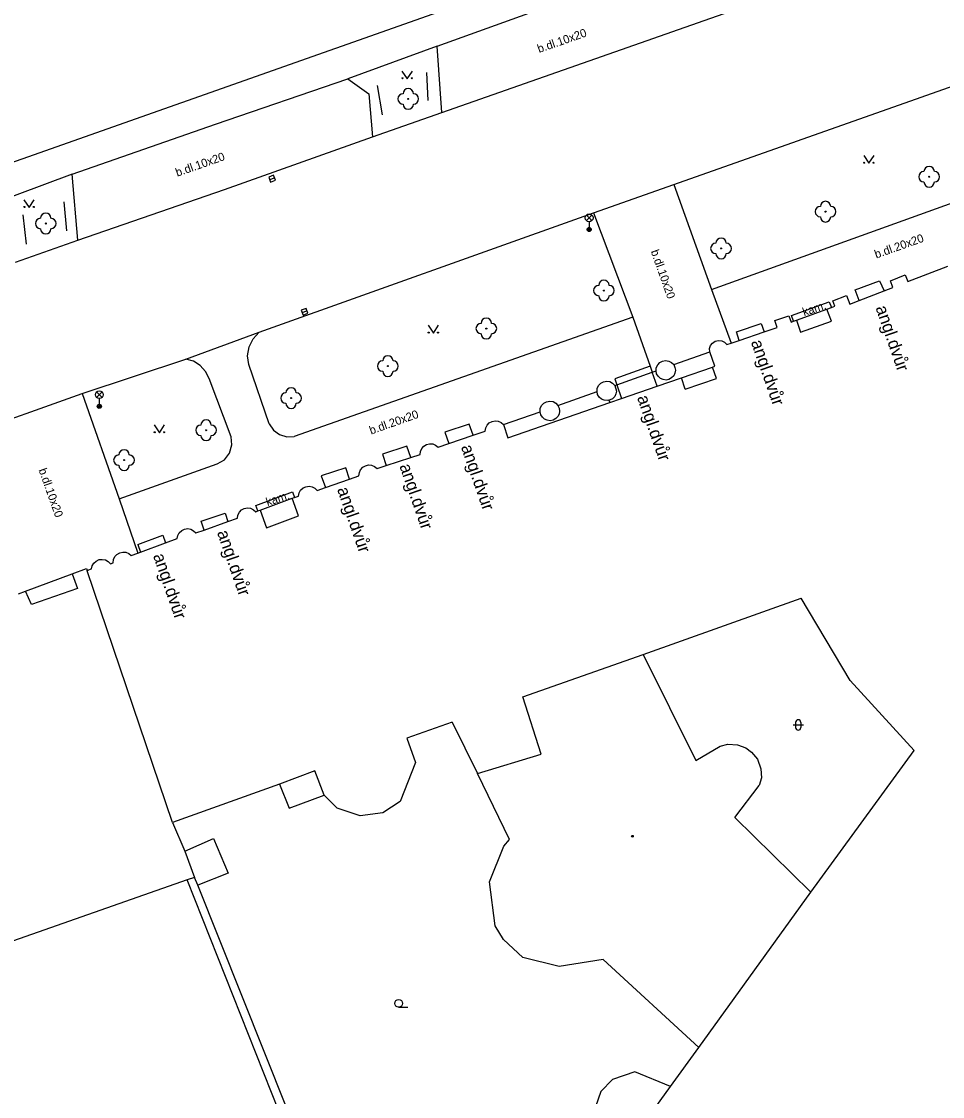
# Model space of a CAD drawing. Extents: x -599770 to -598493, y -1162076 to -1159209.
# Drawn here: x -599015.6 to -598971.2, y -1159443 to -1159391.2 of the extents above; entities that cross this region are included whole.
import ezdxf

# ---------------------------------------------------------------- set-up
doc = ezdxf.new("R2010")
doc.units = 0
doc.layers.add('Podklad', color=7, linetype='Continuous')

msp = doc.modelspace()

# ---------------------------------------------------------------- linework, layer by layer
at = {"layer": 'Podklad'}
for p, q in [((-599003.627, -1159398.855), (-599003.393, -1159398.765)), ((-598988.383, -1159400.83), (-598988.118, -1159400.565)), ((-598988.383, -1159400.565), (-598988.118, -1159400.83)), ((-598988.25, -1159400.885), (-598988.25, -1159401.26)), ((-599002.067, -1159405.265), (-599001.833, -1159405.175)), ((-599011.962, -1159409.35), (-599011.697, -1159409.085)), ((-599011.962, -1159409.085), (-599011.697, -1159409.35)), ((-599011.83, -1159409.405), (-599011.83, -1159409.78)), ((-598978.433, -1159425.128), (-598977.933, -1159425.128)), ((-598978.308, -1159425.003), (-598978.308, -1159425.253)), ((-598978.058, -1159425.003), (-598978.058, -1159425.253)), ((-598997.42, -1159438.727), (-598996.983, -1159438.727))]:
    msp.add_line(p, q, dxfattribs=at)
for points in [[(-599066.08, -1159415.71), (-599053.26, -1159411.13), (-599037.8, -1159405.7), (-598985.61, -1159387.27)], [(-598995.56, -1159392.43), (-598982.51, -1159387.71)], [(-598995.34, -1159395.63), (-598981.16, -1159390.65)], [(-598995.56, -1159392.43), (-598999.87, -1159394)], [(-598995.34, -1159395.63), (-598995.56, -1159392.43)], [(-598984.17, -1159399.1), (-598966.31, -1159392.78)], [(-598997.26, -1159393.625), (-598997.01, -1159394), (-598996.76, -1159393.625)], [(-599013.13, -1159398.59), (-599006.24, -1159396.18), (-598999.87, -1159394)], [(-598999.87, -1159394), (-598998.85, -1159394.73), (-598998.68, -1159396.79)], [(-598996.08, -1159393.69), (-598996.01, -1159395.05)], [(-598998.45, -1159394.32), (-598998.21, -1159395.73)], [(-598998.68, -1159396.79), (-598995.34, -1159395.63)], [(-599012.86, -1159401.77), (-599005.81, -1159399.33), (-598998.68, -1159396.79)], [(-598975.03, -1159397.695), (-598974.78, -1159398.07), (-598974.53, -1159397.695)], [(-599013.13, -1159398.59), (-599017.15, -1159400.09)], [(-599012.86, -1159401.77), (-599013.13, -1159398.59)], [(-598982.36, -1159404.15), (-598967.11, -1159398.66)], [(-598988.04, -1159400.45), (-598984.17, -1159399.1)], [(-598984.17, -1159399.1), (-598982.36, -1159404.15)], [(-599015.46, -1159399.825), (-599015.21, -1159400.2), (-599014.96, -1159399.825)], [(-599013.54, -1159399.92), (-599013.41, -1159401.32)], [(-599015.52, -1159400.55), (-599015.36, -1159401.96)], [(-599004.13, -1159406.2), (-598988.04, -1159400.45)], [(-598988.04, -1159400.45), (-598986.14, -1159405.49)], [(-599015.86, -1159402.84), (-599012.86, -1159401.77)], [(-598973.75, -1159403.73), (-598973.03, -1159403.45)], [(-598973.03, -1159403.45), (-598972.91, -1159403.77)], [(-598972.91, -1159403.77), (-598970.98, -1159403.02)], [(-598975.25, -1159404.68), (-598975.45, -1159404.17), (-598974.27, -1159403.74), (-598974.05, -1159404.21)], [(-598973.63, -1159404.05), (-598973.75, -1159403.73)], [(-598982.36, -1159404.15), (-598981.42, -1159406.73)], [(-598976.52, -1159404.7), (-598975.86, -1159404.44)], [(-598975.86, -1159404.44), (-598975.7, -1159404.85)], [(-598975.7, -1159404.85), (-598975.25, -1159404.68), (-598974.05, -1159404.21), (-598973.63, -1159404.05)], [(-598978.42, -1159405.68), (-598978.51, -1159405.41), (-598976.69, -1159404.74), (-598976.58, -1159405.02)], [(-598978.42, -1159405.68), (-598978.51, -1159405.41), (-598976.69, -1159404.74), (-598976.58, -1159405.01)], [(-598976.8, -1159405.1), (-598976.58, -1159405.01), (-598976.42, -1159404.95)], [(-598976.42, -1159404.95), (-598976.52, -1159404.7)], [(-598986.14, -1159405.49), (-599002.45, -1159411.23)], [(-598986.14, -1159405.49), (-598985.32, -1159407.85), (-598985.22, -1159408.14)], [(-598979.31, -1159405.65), (-598978.63, -1159405.42)], [(-598978.63, -1159405.42), (-598978.53, -1159405.72)], [(-598978.27, -1159405.63), (-598976.8, -1159405.1)], [(-598976.59, -1159405.67), (-598976.8, -1159405.1)], [(-598996, -1159405.875), (-598995.75, -1159406.25), (-598995.5, -1159405.875)], [(-598981.42, -1159406.73), (-598981.03, -1159406.6), (-598979.83, -1159406.19), (-598979.2, -1159405.98)], [(-598981.16, -1159406.19), (-598979.97, -1159405.78), (-598979.83, -1159406.19)], [(-598979.2, -1159405.98), (-598979.31, -1159405.65)], [(-598978.53, -1159405.72), (-598978.42, -1159405.68), (-598978.27, -1159405.63)], [(-598978.27, -1159405.63), (-598978.07, -1159406.2)], [(-598978.07, -1159406.2), (-598976.59, -1159405.67)], [(-599007.67, -1159407.51), (-599004.13, -1159406.2)], [(-599004.63, -1159407.77), (-599004.69, -1159407.34), (-599004.62, -1159406.91), (-599004.43, -1159406.52), (-599004.13, -1159406.2)], [(-598981.03, -1159406.6), (-598981.16, -1159406.19)], [(-598982.45, -1159407), (-598982.4, -1159406.85)], [(-598982.44, -1159407.16), (-598982.45, -1159407)], [(-598982.4, -1159406.85), (-598982.31, -1159406.73)], [(-598982.31, -1159406.73), (-598982.18, -1159406.64)], [(-598982.18, -1159406.64), (-598982.03, -1159406.6)], [(-598982.03, -1159406.6), (-598981.87, -1159406.62)], [(-598981.87, -1159406.62), (-598981.73, -1159406.69)], [(-598981.73, -1159406.69), (-598981.62, -1159406.8)], [(-598981.62, -1159406.8), (-598981.42, -1159406.73)], [(-599012.65, -1159409.16), (-599007.67, -1159407.51)], [(-599006.55, -1159408.44), (-599006.72, -1159408.1), (-599006.98, -1159407.81), (-599007.3, -1159407.61), (-599007.67, -1159407.51)], [(-598984.85, -1159407.67), (-598984.72, -1159407.6)], [(-598984.72, -1159407.6), (-598984.57, -1159407.57)], [(-598984.57, -1159407.57), (-598984.42, -1159407.6)], [(-598984.42, -1159407.6), (-598984.29, -1159407.66)], [(-598984.18, -1159407.77), (-598982.44, -1159407.16)], [(-598982.2, -1159407.85), (-598982.44, -1159407.16)], [(-599003.66, -1159410.62), (-599004.63, -1159407.77)], [(-598985.32, -1159407.85), (-598987.01, -1159408.46), (-598986.91, -1159408.74)], [(-598986.91, -1159408.74), (-598985.22, -1159408.14)], [(-598985.22, -1159408.14), (-598985.03, -1159408.07)], [(-598984.98, -1159408.81), (-598985.22, -1159408.14)], [(-598985.03, -1159408.07), (-598985.02, -1159407.92)], [(-598985, -1159408.21), (-598985.03, -1159408.07)], [(-598985.02, -1159407.92), (-598984.95, -1159407.78)], [(-598984.95, -1159407.78), (-598984.85, -1159407.67)], [(-598984.29, -1159407.66), (-598984.18, -1159407.77)], [(-598984.18, -1159407.77), (-598984.12, -1159407.9)], [(-598984.12, -1159407.9), (-598984.1, -1159408.04)], [(-598984.1, -1159408.04), (-598984.12, -1159408.18)], [(-598983.81, -1159408.41), (-598982.31, -1159407.89)], [(-598982.31, -1159407.89), (-598982.2, -1159407.85)], [(-598982.12, -1159408.43), (-598982.31, -1159407.89)], [(-599005.49, -1159411.24), (-599006.55, -1159408.44)], [(-598992.16, -1159411.29), (-598987.26, -1159409.6), (-598986.69, -1159409.4), (-598984.98, -1159408.81), (-598983.81, -1159408.41)], [(-598987.8, -1159408.77), (-598987.69, -1159408.66)], [(-598987.69, -1159408.66), (-598987.56, -1159408.59)], [(-598987.56, -1159408.59), (-598987.4, -1159408.56)], [(-598987.4, -1159408.56), (-598987.25, -1159408.58)], [(-598987.25, -1159408.58), (-598987.12, -1159408.66)], [(-598987.12, -1159408.66), (-598987.01, -1159408.77)], [(-598984.93, -1159408.33), (-598985, -1159408.21)], [(-598984.82, -1159408.43), (-598984.93, -1159408.33)], [(-598984.69, -1159408.49), (-598984.82, -1159408.43)], [(-598984.55, -1159408.51), (-598984.69, -1159408.49)], [(-598984.41, -1159408.48), (-598984.55, -1159408.51)], [(-598984.28, -1159408.41), (-598984.41, -1159408.48)], [(-598984.18, -1159408.31), (-598984.28, -1159408.41)], [(-598984.12, -1159408.18), (-598984.18, -1159408.31)], [(-598983.62, -1159408.95), (-598983.81, -1159408.41)], [(-598983.62, -1159408.95), (-598982.12, -1159408.43)], [(-599018.33, -1159411.18), (-599012.65, -1159409.16)], [(-599012.65, -1159409.16), (-599010.88, -1159414.23)], [(-598989.75, -1159409.74), (-598987.87, -1159409.07)], [(-598987.87, -1159409.07), (-598987.86, -1159408.92)], [(-598987.84, -1159409.21), (-598987.87, -1159409.07)], [(-598987.86, -1159408.92), (-598987.8, -1159408.77)], [(-598986.96, -1159409.18), (-598987.02, -1159409.31)], [(-598987.01, -1159408.77), (-598986.91, -1159408.74)], [(-598987.01, -1159408.77), (-598986.93, -1159409.04)], [(-598986.93, -1159409.04), (-598986.96, -1159409.18)], [(-598986.915, -1159408.736), (-598986.69, -1159409.4)], [(-598990.54, -1159409.74), (-598990.43, -1159409.63)], [(-598990.43, -1159409.63), (-598990.3, -1159409.56)], [(-598990.3, -1159409.56), (-598990.14, -1159409.53)], [(-598990.14, -1159409.53), (-598989.99, -1159409.55)], [(-598989.99, -1159409.55), (-598989.86, -1159409.63)], [(-598989.86, -1159409.63), (-598989.75, -1159409.74)], [(-598987.76, -1159409.33), (-598987.84, -1159409.21)], [(-598987.66, -1159409.43), (-598987.76, -1159409.33)], [(-598987.53, -1159409.48), (-598987.66, -1159409.43)], [(-598987.39, -1159409.5), (-598987.53, -1159409.48)], [(-598987.24, -1159409.47), (-598987.3, -1159409.48), (-598987.39, -1159409.5)], [(-598987.3, -1159409.48), (-598987.26, -1159409.6)], [(-598987.12, -1159409.41), (-598987.24, -1159409.47)], [(-598987.02, -1159409.31), (-598987.12, -1159409.41)], [(-598992.38, -1159410.66), (-598990.61, -1159410.04)], [(-598990.61, -1159410.04), (-598990.6, -1159409.89)], [(-598990.58, -1159410.18), (-598990.61, -1159410.04)], [(-598990.6, -1159409.89), (-598990.54, -1159409.74)], [(-598990.5, -1159410.3), (-598990.58, -1159410.18)], [(-598989.7, -1159410.15), (-598989.76, -1159410.27)], [(-598989.75, -1159409.74), (-598989.69, -1159409.87)], [(-598989.67, -1159410.01), (-598989.7, -1159410.15)], [(-598989.69, -1159409.87), (-598989.67, -1159410.01)], [(-599009.19, -1159410.675), (-599008.94, -1159411.05), (-599008.69, -1159410.675)], [(-599003.66, -1159410.62), (-599003.45, -1159410.92), (-599003.16, -1159411.13), (-599002.81, -1159411.24), (-599002.45, -1159411.23)], [(-598993.84, -1159411.17), (-598994.02, -1159410.64), (-598995.19, -1159411.03), (-598995, -1159411.57)], [(-598993.23, -1159410.82), (-598993.16, -1159410.69)], [(-598993.16, -1159410.69), (-598993.06, -1159410.58)], [(-598993.06, -1159410.58), (-598992.92, -1159410.51)], [(-598992.92, -1159410.51), (-598992.78, -1159410.48)], [(-598992.78, -1159410.48), (-598992.63, -1159410.5)], [(-598992.63, -1159410.5), (-598992.49, -1159410.56)], [(-598992.49, -1159410.56), (-598992.38, -1159410.66)], [(-598992.38, -1159410.66), (-598992.16, -1159411.29)], [(-598990.4, -1159410.39), (-598990.5, -1159410.3)], [(-598990.27, -1159410.45), (-598990.4, -1159410.39)], [(-598990.13, -1159410.47), (-598990.27, -1159410.45)], [(-598989.99, -1159410.44), (-598990.13, -1159410.47)], [(-598989.86, -1159410.37), (-598989.99, -1159410.44)], [(-598989.76, -1159410.27), (-598989.86, -1159410.37)], [(-599006.16, -1159412.55), (-599005.81, -1159412.35), (-599005.56, -1159412.03), (-599005.45, -1159411.64), (-599005.49, -1159411.24)], [(-598995.52, -1159411.75), (-598995, -1159411.57), (-598993.84, -1159411.17), (-598993.26, -1159410.97)], [(-598993.26, -1159410.97), (-598993.23, -1159410.82)], [(-598996.84, -1159412.25), (-598997.02, -1159411.69), (-598998.2, -1159412.09), (-598998.02, -1159412.63)], [(-598996.31, -1159411.81), (-598996.21, -1159411.69)], [(-598996.21, -1159411.69), (-598996.08, -1159411.62)], [(-598996.08, -1159411.62), (-598995.93, -1159411.58)], [(-598995.93, -1159411.58), (-598995.78, -1159411.59)], [(-598995.78, -1159411.59), (-598995.64, -1159411.65)], [(-598995.64, -1159411.65), (-598995.52, -1159411.75)], [(-598998.46, -1159412.77), (-598998.02, -1159412.63), (-598996.84, -1159412.25), (-598996.39, -1159412.1)], [(-598996.39, -1159412.1), (-598996.37, -1159411.95)], [(-598996.37, -1159411.95), (-598996.31, -1159411.81)], [(-599010.88, -1159414.23), (-599006.16, -1159412.55)], [(-598999.78, -1159413.28), (-598999.97, -1159412.74), (-599001.15, -1159413.12), (-599000.95, -1159413.69)], [(-598999.25, -1159412.83), (-598999.15, -1159412.71)], [(-598999.15, -1159412.71), (-598999.02, -1159412.64)], [(-598999.02, -1159412.64), (-598998.87, -1159412.6)], [(-598998.87, -1159412.6), (-598998.72, -1159412.61)], [(-598998.72, -1159412.61), (-598998.58, -1159412.67)], [(-598998.58, -1159412.67), (-598998.46, -1159412.77)], [(-599001.34, -1159413.83), (-599000.95, -1159413.69), (-598999.78, -1159413.28), (-598999.33, -1159413.12)], [(-598999.33, -1159413.12), (-598999.31, -1159412.97)], [(-598999.31, -1159412.97), (-598999.25, -1159412.83)], [(-599002.21, -1159413.95), (-599002.14, -1159413.82)], [(-599002.14, -1159413.82), (-599002.02, -1159413.71)], [(-599002.02, -1159413.71), (-599001.89, -1159413.65)], [(-599001.89, -1159413.65), (-599001.73, -1159413.62)], [(-599001.73, -1159413.62), (-599001.58, -1159413.65)], [(-599001.58, -1159413.65), (-599001.45, -1159413.72)], [(-599001.45, -1159413.72), (-599001.34, -1159413.83)], [(-599010.88, -1159414.23), (-599009.98, -1159416.85)], [(-599004.2, -1159414.82), (-599004.3, -1159414.56), (-599002.53, -1159413.89), (-599002.44, -1159414.17)], [(-599004.2, -1159414.82), (-599004.3, -1159414.56), (-599002.53, -1159413.89), (-599002.44, -1159414.17)], [(-599004.08, -1159414.78), (-599002.54, -1159414.2)], [(-599002.54, -1159414.2), (-599002.44, -1159414.17), (-599002.24, -1159414.1)], [(-599002.24, -1159415.05), (-599002.54, -1159414.2)], [(-599002.24, -1159414.1), (-599002.21, -1159413.95)], [(-599005.16, -1159415.02), (-599005.09, -1159414.88)], [(-599005.09, -1159414.88), (-599004.99, -1159414.77)], [(-599004.99, -1159414.77), (-599004.85, -1159414.7)], [(-599004.85, -1159414.7), (-599004.7, -1159414.67)], [(-599004.7, -1159414.67), (-599004.55, -1159414.69)], [(-599004.55, -1159414.69), (-599004.41, -1159414.76)], [(-599004.41, -1159414.76), (-599004.3, -1159414.86)], [(-599004.3, -1159414.86), (-599004.2, -1159414.82), (-599004.08, -1159414.78)], [(-599004.08, -1159414.78), (-599003.78, -1159415.63)], [(-599007.18, -1159415.88), (-599006.78, -1159415.74), (-599005.64, -1159415.33), (-599005.18, -1159415.17)], [(-599006.78, -1159415.74), (-599006.93, -1159415.31), (-599005.78, -1159414.93), (-599005.64, -1159415.33)], [(-599005.18, -1159415.17), (-599005.16, -1159415.02)], [(-599003.78, -1159415.63), (-599002.24, -1159415.05)], [(-599008.05, -1159416), (-599007.98, -1159415.87)], [(-599007.98, -1159415.87), (-599007.86, -1159415.76)], [(-599007.86, -1159415.76), (-599007.73, -1159415.7)], [(-599007.73, -1159415.7), (-599007.57, -1159415.67)], [(-599007.57, -1159415.67), (-599007.42, -1159415.7)], [(-599007.42, -1159415.7), (-599007.29, -1159415.77)], [(-599007.29, -1159415.77), (-599007.18, -1159415.88)], [(-599009.98, -1159416.43), (-599008.77, -1159415.99), (-599008.64, -1159416.36)], [(-599009.98, -1159416.85), (-599009.85, -1159416.8), (-599008.64, -1159416.36), (-599008.08, -1159416.15)], [(-599009.98, -1159416.43), (-599009.85, -1159416.8)], [(-599008.08, -1159416.15), (-599008.05, -1159416)], [(-599011.08, -1159417.02), (-599010.98, -1159416.91)], [(-599010.98, -1159416.91), (-599010.85, -1159416.83)], [(-599010.85, -1159416.83), (-599010.7, -1159416.8)], [(-599010.7, -1159416.8), (-599010.55, -1159416.81)], [(-599010.55, -1159416.81), (-599010.41, -1159416.87)], [(-599010.41, -1159416.87), (-599010.29, -1159416.97)], [(-599010.29, -1159416.97), (-599009.98, -1159416.85)], [(-599012.2, -1159417.61), (-599012.17, -1159417.46)], [(-599012.17, -1159417.46), (-599012.09, -1159417.33)], [(-599012.09, -1159417.33), (-599011.98, -1159417.23)], [(-599011.98, -1159417.23), (-599011.84, -1159417.16)], [(-599011.84, -1159417.16), (-599011.69, -1159417.15)], [(-599011.69, -1159417.15), (-599011.54, -1159417.18)], [(-599011.54, -1159417.18), (-599011.41, -1159417.25)], [(-599011.41, -1159417.25), (-599011.3, -1159417.36)], [(-599011.3, -1159417.36), (-599011.16, -1159417.31)], [(-599011.16, -1159417.31), (-599011.14, -1159417.16)], [(-599011.14, -1159417.16), (-599011.08, -1159417.02)], [(-599015.72, -1159418.81), (-599015.39, -1159418.69), (-599013.13, -1159417.84), (-599012.45, -1159417.59)], [(-599013.13, -1159417.84), (-599012.88, -1159418.55), (-599015.09, -1159419.32), (-599015.39, -1159418.69)], [(-599012.45, -1159417.59), (-599012.41, -1159417.7)], [(-599012.2, -1159417.61), (-599012.41, -1159417.7)], [(-599008.31, -1159429.83), (-599012.41, -1159417.7)], [(-598985.65, -1159421.73), (-598978.05, -1159419.02)], [(-598975.69, -1159422.99), (-598978.05, -1159419.02)], [(-598991.44, -1159423.78), (-598985.65, -1159421.73)], [(-598985.65, -1159421.73), (-598983.12, -1159426.84)], [(-598972.6, -1159426.36), (-598975.69, -1159422.99)], [(-598990.56, -1159426.53), (-598991.44, -1159423.78)], [(-598994.84, -1159424.99), (-598997.03, -1159425.77)], [(-598994.84, -1159424.99), (-598993.63, -1159427.47)], [(-598997.03, -1159425.77), (-598996.61, -1159426.94)], [(-598983.12, -1159426.84), (-598981.95, -1159426.15)], [(-598981.95, -1159426.15), (-598981.57, -1159426.06)], [(-598981.57, -1159426.06), (-598981.11, -1159426.08)], [(-598981.11, -1159426.08), (-598980.71, -1159426.23)], [(-598980.71, -1159426.23), (-598980.43, -1159426.43)], [(-598993.63, -1159427.47), (-598990.56, -1159426.53)], [(-598980.43, -1159426.43), (-598980.14, -1159426.78)], [(-598980.14, -1159426.78), (-598979.98, -1159427.24)], [(-598977.57, -1159433.18), (-598972.6, -1159426.36)], [(-598996.61, -1159426.94), (-598997.34, -1159428.81)], [(-598979.98, -1159427.24), (-598979.96, -1159427.68)], [(-599001.46, -1159427.34), (-599003.16, -1159427.98)], [(-599001, -1159428.51), (-599001.46, -1159427.34)], [(-598992.08, -1159430.65), (-598993.63, -1159427.47)], [(-598979.96, -1159427.68), (-598980.07, -1159428.05)], [(-599003.16, -1159427.98), (-599008.31, -1159429.83)], [(-599003.16, -1159427.98), (-599002.69, -1159429.14)], [(-598981.24, -1159429.59), (-598980.07, -1159428.05)], [(-599002.69, -1159429.14), (-599001, -1159428.51)], [(-599000.38, -1159429.13), (-599001, -1159428.51)], [(-598997.34, -1159428.81), (-598998.18, -1159429.36)], [(-598999.28, -1159429.5), (-599000.38, -1159429.13)], [(-598998.18, -1159429.36), (-598999.28, -1159429.5)], [(-599008.31, -1159429.83), (-599007.72, -1159431.2)], [(-598977.57, -1159433.18), (-598981.24, -1159429.59)], [(-599007.72, -1159431.2), (-599006.34, -1159430.6)], [(-599006.34, -1159430.6), (-599005.62, -1159432.26)], [(-598992.35, -1159430.96), (-598992.08, -1159430.65)], [(-599007.72, -1159431.2), (-599007.25, -1159432.47)], [(-598993.04, -1159432.69), (-598992.35, -1159430.96)], [(-599007.25, -1159432.47), (-599007.6, -1159432.58)], [(-599007.09, -1159432.85), (-599007.25, -1159432.47)], [(-599005.62, -1159432.26), (-599007.09, -1159432.85)], [(-599007.6, -1159432.58), (-599022.28, -1159437.74)], [(-599003.17, -1159443.76), (-599007.6, -1159432.58)], [(-599002.82, -1159443.55), (-599007.09, -1159432.85)], [(-598992.78, -1159434.81), (-598993.04, -1159432.69)], [(-598982.97, -1159440.67), (-598977.57, -1159433.18)], [(-598992.38, -1159435.47), (-598992.78, -1159434.81)], [(-598991.45, -1159436.33), (-598992.38, -1159435.47)], [(-598989.69, -1159436.76), (-598991.45, -1159436.33)], [(-598987.58, -1159436.42), (-598989.69, -1159436.76)], [(-598982.97, -1159440.67), (-598987.58, -1159436.42)], [(-598984.34, -1159442.55), (-598982.97, -1159440.67)], [(-598987.13, -1159442.21), (-598987.68, -1159442.78)], [(-598986.05, -1159441.83), (-598987.13, -1159442.21)], [(-598984.34, -1159442.55), (-598986.05, -1159441.83)], [(-598987.68, -1159442.78), (-598988.19, -1159444.22)], [(-598986.82, -1159446), (-598984.34, -1159442.55)]]:
    msp.add_lwpolyline(points, dxfattribs=at)
for points in [[(-599003.582, -1159398.972), (-599003.348, -1159398.882), (-599003.438, -1159398.648), (-599003.672, -1159398.738)], [(-599002.022, -1159405.382), (-599001.788, -1159405.291), (-599001.878, -1159405.058), (-599002.112, -1159405.148)]]:
    msp.add_lwpolyline(points, close=True, dxfattribs=at)
for centre, radius in [((-598997.235, -1159393.975), 0.025), ((-598996.785, -1159393.975), 0.025), ((-598996.96, -1159394.97), 0.025), ((-598975.005, -1159398.045), 0.025), ((-598974.555, -1159398.045), 0.025), ((-598971.88, -1159398.72), 0.025), ((-599015.435, -1159400.175), 0.025), ((-599014.985, -1159400.175), 0.025), ((-598976.87, -1159400.4), 0.025), ((-598988.25, -1159400.698), 0.188), ((-599014.41, -1159400.97), 0.025), ((-598988.25, -1159401.26), 0.1), ((-598988.25, -1159401.26), 0.0723), ((-598988.25, -1159401.26), 0.0438), ((-598981.9, -1159402.17), 0.025), ((-598987.54, -1159404.2), 0.025), ((-598993.2, -1159406.03), 0.025), ((-598995.975, -1159406.225), 0.025), ((-598995.525, -1159406.225), 0.025), ((-598997.94, -1159407.84), 0.025), ((-599011.83, -1159409.218), 0.188), ((-599011.83, -1159409.78), 0.1), ((-599002.6, -1159409.38), 0.025), ((-599011.83, -1159409.78), 0.0723), ((-599011.83, -1159409.78), 0.0438), ((-599009.165, -1159411.025), 0.025), ((-599008.715, -1159411.025), 0.025), ((-599006.69, -1159410.93), 0.025), ((-599010.64, -1159412.37), 0.025), ((-598986.17, -1159430.49), 0.045), ((-598986.17, -1159430.49), 0.0199), ((-598997.42, -1159438.54), 0.188)]:
    msp.add_circle(centre, radius, dxfattribs=at)
for centre, radius, start, end in [((-598996.96, -1159394.72), 0.25, 0, 180), ((-598997.21, -1159394.97), 0.25, 90, 270), ((-598996.71, -1159394.97), 0.25, 270, 90), ((-598996.96, -1159395.22), 0.25, 180, 0), ((-598971.88, -1159398.47), 0.25, 0, 180), ((-598972.13, -1159398.72), 0.25, 90, 270), ((-598971.63, -1159398.72), 0.25, 270, 90), ((-598971.88, -1159398.97), 0.25, 180, 0), ((-598977.12, -1159400.4), 0.25, 90, 270), ((-598976.87, -1159400.15), 0.25, 0, 180), ((-598976.62, -1159400.4), 0.25, 270, 90), ((-599014.66, -1159400.97), 0.25, 90, 270), ((-599014.41, -1159400.72), 0.25, 0, 180), ((-599014.16, -1159400.97), 0.25, 270, 90), ((-598976.87, -1159400.65), 0.25, 180, 0), ((-599014.41, -1159401.22), 0.25, 180, 0), ((-598982.15, -1159402.17), 0.25, 90, 270), ((-598981.9, -1159401.92), 0.25, 0, 180), ((-598981.65, -1159402.17), 0.25, 270, 90), ((-598981.9, -1159402.42), 0.25, 180, 0), ((-598987.79, -1159404.2), 0.25, 90, 270), ((-598987.54, -1159403.95), 0.25, 0, 180), ((-598987.29, -1159404.2), 0.25, 270, 90), ((-598987.54, -1159404.45), 0.25, 180, 0), ((-598993.2, -1159405.78), 0.25, 0, 180), ((-598993.45, -1159406.03), 0.25, 90, 270), ((-598992.95, -1159406.03), 0.25, 270, 90), ((-598993.2, -1159406.28), 0.25, 180, 0), ((-598998.19, -1159407.84), 0.25, 90, 270), ((-598997.94, -1159407.59), 0.25, 0, 180), ((-598997.69, -1159407.84), 0.25, 270, 90), ((-598997.94, -1159408.09), 0.25, 180, 0), ((-599002.85, -1159409.38), 0.25, 90, 270), ((-599002.6, -1159409.13), 0.25, 0, 180), ((-599002.35, -1159409.38), 0.25, 270, 90), ((-599002.6, -1159409.63), 0.25, 180, 0), ((-599006.94, -1159410.93), 0.25, 90, 270), ((-599006.69, -1159410.68), 0.25, 0, 180), ((-599006.44, -1159410.93), 0.25, 270, 90), ((-599006.69, -1159411.18), 0.25, 180, 0), ((-599010.89, -1159412.37), 0.25, 90, 270), ((-599010.64, -1159412.12), 0.25, 0, 180), ((-599010.39, -1159412.37), 0.25, 270, 90), ((-599010.64, -1159412.62), 0.25, 180, 0), ((-598978.183, -1159425.003), 0.125, 0, 180), ((-598978.183, -1159425.253), 0.125, 180, 0)]:
    msp.add_arc(centre, radius, start, end, dxfattribs=at)

# ---------------------------------------------------------------- texts
for s, height, rotation, p in [('b.dl.10x20', 0.4, 19.3035, (-598990.66, -1159392.76)), ('b.dl.10x20', 0.4, 19.3035, (-599008.08, -1159398.72)), ('b.dl.20x20', 0.4, 19.5159, (-598974.43, -1159402.66)), ('b.dl.10x20', 0.4, 289.5159, (-598985.29, -1159402.31)), ('kam.', 0.4, 18.5793, (-598977.9, -1159405.44)), ('angl.dvůr', 0.6, 289.1291, (-598974.47, -1159405.03)), ('angl.dvůr', 0.6, 289.1291, (-598980.47, -1159406.68)), ('angl.dvůr', 0.6, 289.1291, (-598985.95, -1159409.35)), ('b.dl.20x20', 0.4, 19.5159, (-598998.75, -1159411.14)), ('angl.dvůr', 0.6, 289.1291, (-598994.43, -1159411.73)), ('b.dl.10x20', 0.4, 289.5159, (-599014.76, -1159412.84)), ('angl.dvůr', 0.6, 289.1291, (-598997.39, -1159412.65)), ('angl.dvůr', 0.6, 289.1291, (-599000.39, -1159413.77)), ('kam.', 0.4, 18.5793, (-599003.73, -1159414.59)), ('angl.dvůr', 0.6, 289.1291, (-599006.17, -1159415.85)), ('angl.dvůr', 0.6, 289.1291, (-599009.25, -1159416.97))]:
    msp.add_text(s, height=height, rotation=rotation, dxfattribs=at).set_placement(p)

doc.saveas('drawing.dxf')
